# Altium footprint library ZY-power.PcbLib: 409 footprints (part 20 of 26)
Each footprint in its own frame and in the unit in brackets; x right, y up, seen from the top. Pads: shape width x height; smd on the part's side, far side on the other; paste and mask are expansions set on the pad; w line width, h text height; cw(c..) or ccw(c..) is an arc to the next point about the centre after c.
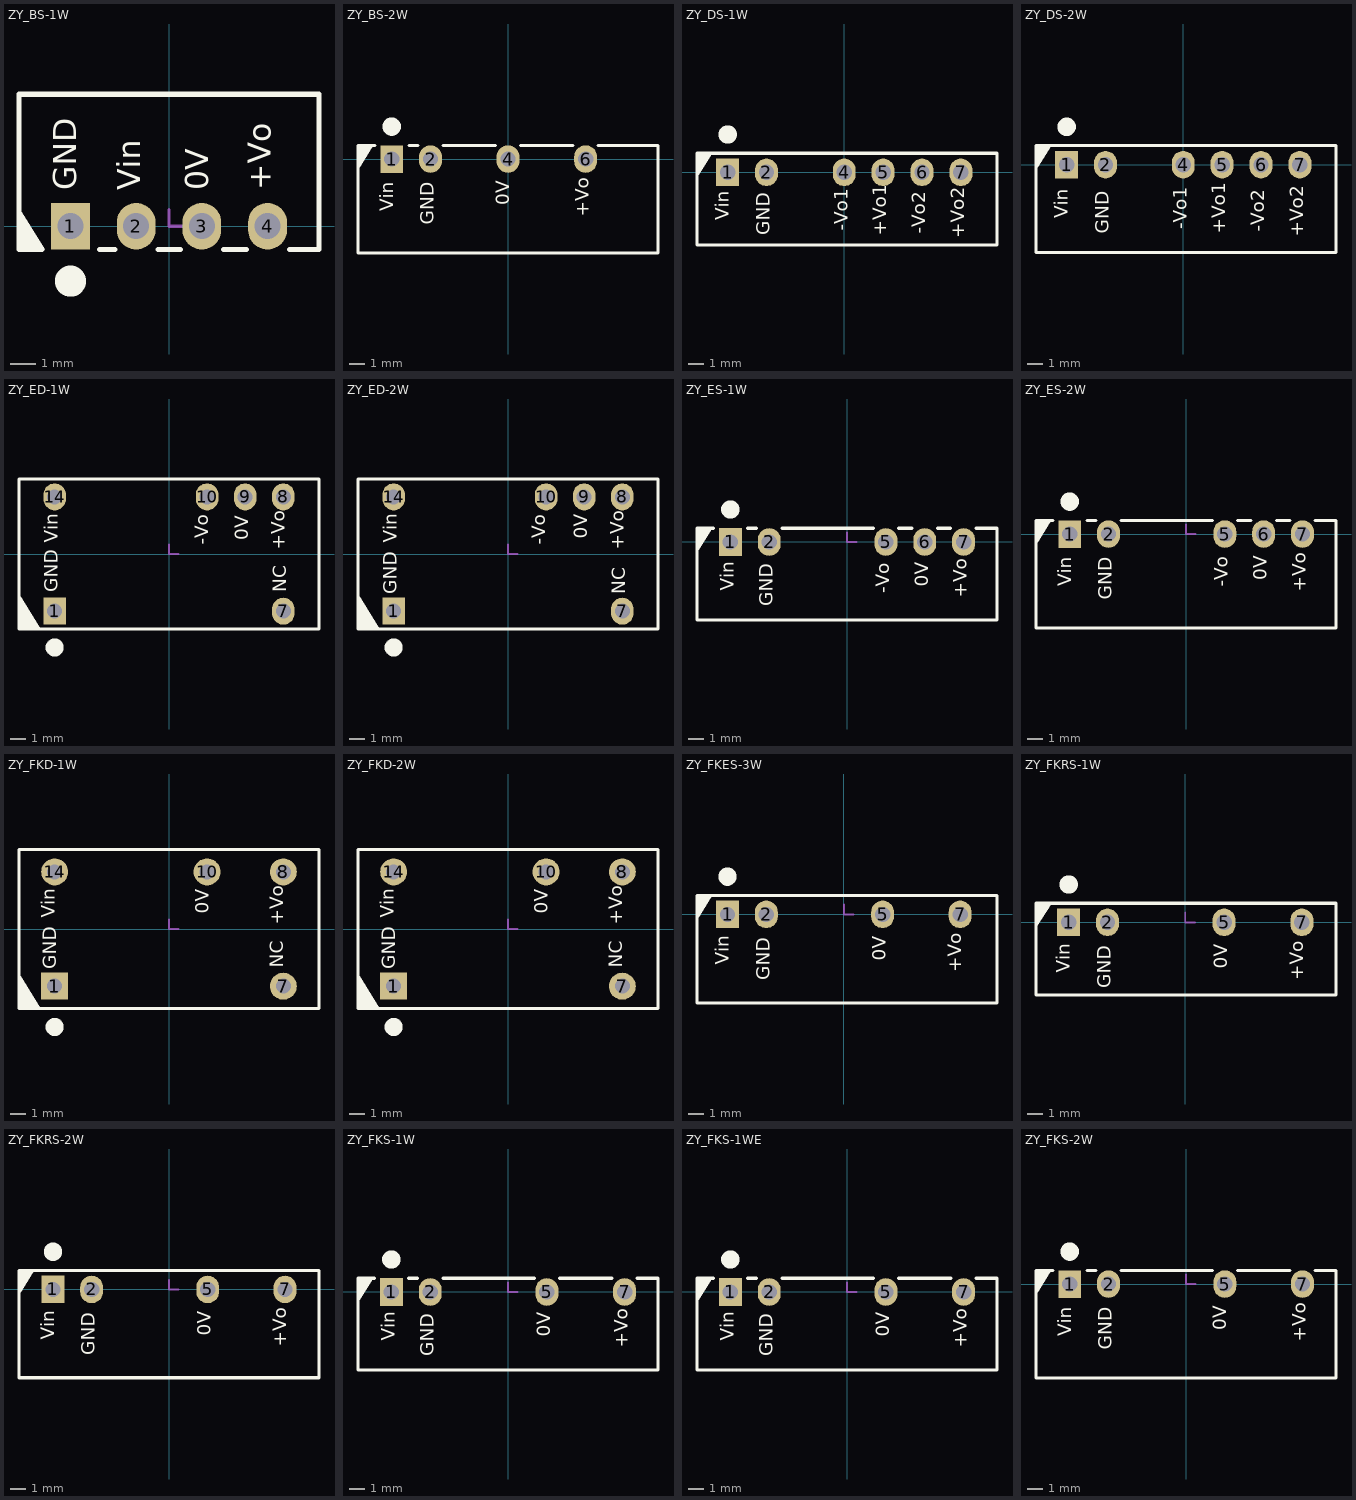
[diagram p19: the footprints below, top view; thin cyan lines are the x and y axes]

## ZY_BS-1W [mm] "定压输入隔离非稳压单输出"
height 10.1
pads (4):
  rect 1.5x1.8 hole 1: 1(-3.81,0)
  oval 1.5x1.8 hole 1: 2(-1.27,0) 3(1.27,0) 4(3.81,0)
Top Overlay:
  circle w1: c-3.81,-2.125 r0.1
  region: -5.8,0.686 -5.8,-0.889 -4.813,-0.889
  lines w0.2: -4.91,-0.9 -5.8,-0.9 -5.8,5.1 5.8,5.1 5.8,-0.9 4.656,-0.9 ; -2.69,-0.9 -2.09,-0.9 ; -0.424,-0.9 0.45,-0.9 ; 2.116,-0.9 2.99,-0.9
  text "GND" at -3.302,1.396 h1.52
  text "Vin" at -0.813,1.397 h1.52
  text "0V" at 1.803,1.396 h1.52
  text "+Vo" at 4.216,1.396 h1.52
Mechanical 15:
  lines w0.127: 0,0.635 0,0 0.635,0
3D body "zhenjao01.stp": height 8.36, standoff -4.08, extent 3.11,-0.12 4.51,1.48
3D body "zhenjao01.stp": height 8.36, standoff -4.08, extent 0.57,-0.12 1.97,1.48
3D body "zhenjao01.stp": height 8.36, standoff -4.08, extent -1.97,-0.12 -0.57,1.48
3D body: height 10.1, standoff 0, extent -5.8,-0.9 5.8,5.1
3D body "zhenjao01.stp": height 8.36, standoff -4.08, extent -4.51,-0.12 -3.11,1.48

## ZY_BS-2W [mm] "定压输入隔离非稳压单输出"
height 10.1
pads (4):
  rect 1.5x1.8 hole 1: 1(-7.62,0)
  oval 1.5x1.8 hole 1: 2(-5.08,0) 4(0,0) 6(5.08,0)
Top Overlay:
  circle w1: c-7.62,2.125 r0.1
  region: -9.83,-0.686 -9.83,0.9 -8.836,0.9
  lines w0.2: -8.72,0.9 -9.83,0.9 -9.83,-6.15 9.82,-6.15 9.82,0.9 5.9,0.9 ; -6.5,0.9 -5.9,0.9 ; -4.26,0.9 -0.82,0.9 ; 0.82,0.9 4.26,0.9
  text "+Vo" at 5.588,-3.776 h1.52
  text "0V" at 0.381,-3.036 h1.52
  text "GND" at -4.572,-4.318 h1.52
  text "Vin" at -7.239,-3.435 h1.52
Mechanical 15:
  lines w0.127: 0,0.635 0,0 0.635,0
3D body: height 10.1, standoff 0, extent -9.83,-6.15 9.77,0.9
3D body "zhenjao01.stp": height 8.36, standoff -4.08, extent 4.38,-1.48 5.78,0.12
3D body "zhenjao01.stp": height 8.36, standoff -4.08, extent -0.7,-1.48 0.7,0.12
3D body "zhenjao01.stp": height 8.36, standoff -4.08, extent -5.78,-1.48 -4.38,0.12
3D body "zhenjao01.stp": height 8.36, standoff -4.08, extent -8.32,-1.48 -6.92,0.12

## ZY_DS-1W [mm]
pads (6):
  rect 1.5x1.8 hole 1: 1(-7.62,0)
  oval 1.5x1.8 hole 1: 2(-5.08,0) 4(0,0) 5(2.54,0) 6(5.08,0) 7(7.62,0)
Top Overlay:
  circle w1: c-7.62,2.475 r0.1
  region: -9.62,-0.336 -9.62,1.25 -8.626,1.25
  lines w0.2: -9.62,-4.75 9.98,-4.75 9.98,1.25 -9.62,1.25 -9.62,-4.75
  text "-Vo1" at 0.508,-3.828 h1.52
  text "Vin" at -7.239,-3.113 h1.52
  text "GND" at -4.572,-4.123 h1.52
  text "+Vo1" at 3.048,-4.14 h1.52
  text "-Vo2" at 5.588,-4.006 h1.52
  text "+Vo2" at 8.128,-4.318 h1.52
Mechanical 15:
  lines w0.127: 0,0.635 0,0 0.635,0

## ZY_DS-2W [mm] "定压输入隔离非稳压双输出"
height 10
pads (6):
  rect 1.5x1.8 hole 1: 1(-7.62,0)
  oval 1.5x1.8 hole 1: 2(-5.08,0) 4(0,0) 5(2.54,0) 6(5.08,0) 7(7.62,0)
Top Overlay:
  circle w1: c-7.62,2.475 r0.1
  region: -9.62,-0.336 -9.62,1.25 -8.626,1.25
  lines w0.2: -9.62,-5.75 -9.62,1.25 9.98,1.25 9.98,-5.75 -9.62,-5.75
  text "+Vo2" at 8.128,-4.699 h1.52
  text "-Vo2" at 5.588,-4.387 h1.52
  text "+Vo1" at 3.048,-4.521 h1.52
  text "GND" at -4.572,-4.504 h1.52
  text "Vin" at -7.239,-3.494 h1.52
  text "-Vo1" at 0.508,-4.209 h1.52
Mechanical 15:
  lines w0.127: 0,0.635 0,0 0.635,0

## ZY_ED-1W [mm] "定压输入隔离非稳压正、负输出"
height 7
pads (6):
  rect 1.5x1.8 hole 1: 1(-7.62,-3.81)
  oval 1.5x1.8 hole 1: 7(7.62,-3.81) 8(7.62,3.81) 9(5.08,3.81) 10(2.54,3.81) 14(-7.62,3.81)
Top Overlay:
  circle w1: c-7.62,-6.225 r0.1
  region: -10,-2.67 -10,-5 -8.54,-5
  lines w0.2: -10,-5 10,-5 10,5 -10,5 -10,-5
  text "+Vo" at 8.001,0.294 h1.52
  text "0V" at 5.588,0.907 h1.52
  text "-Vo" at 2.921,0.606 h1.52
  text "Vin" at -7.112,0.762 h1.52
  text "NC" at 8.128,-2.54 h1.52
  text "GND" at -7.112,-2.54 h1.52
Mechanical 15:
  lines w0.127: 0,0.635 0,0 0.635,0

## ZY_ED-2W [mm]
height 8
pads (6):
  rect 1.5x1.8 hole 1: 1(-7.62,-3.81)
  oval 1.5x1.8 hole 1: 7(7.62,-3.81) 8(7.62,3.81) 9(5.08,3.81) 10(2.54,3.81) 14(-7.62,3.81)
Top Overlay:
  circle w1: c-7.62,-6.225 r0.1
  region: -10,-2.67 -10,-5 -8.54,-5
  lines w0.2: -10,-5 -10,5 10,5 10,-5 -10,-5
  text "GND" at -7.112,-2.667 h1.52
  text "NC" at 8.128,-2.667 h1.52
  text "Vin" at -7.112,0.762 h1.52
  text "-Vo" at 2.794,0.606 h1.52
  text "0V" at 5.588,1.034 h1.52
  text "+Vo" at 8.001,0.294 h1.52
Mechanical 15:
  lines w0.127: 0,0.635 0,0 0.635,0

## ZY_ES-1W [mm] "定压输入隔离非稳压正、负输出"
height 10.1
pads (5):
  rect 1.5x1.8 hole 1: 1(-7.62,0)
  oval 1.5x1.8 hole 1: 2(-5.08,0) 5(2.54,0) 6(5.08,0) 7(7.62,0)
Top Overlay:
  circle w1: c-7.62,2.125 r0.1
  region: -9.8,-0.686 -9.8,0.9 -8.806,0.9
  lines w0.2: -8.72,0.9 -9.8,0.9 -9.8,-5.1 9.8,-5.1 9.8,0.9 8.44,0.9 ; -6.5,0.9 -5.9,0.9 ; -4.26,0.9 1.72,0.9 ; 3.36,0.9 4.234,0.9 ; 5.9,0.9 6.774,0.9
  text "0V" at 5.588,-2.909 h1.52
  text "-Vo" at 3.048,-3.337 h1.52
  text "Vin" at -7.112,-3.181 h1.52
  text "GND" at -4.572,-4.191 h1.52
  text "+Vo" at 8.128,-3.649 h1.52
Mechanical 15:
  lines w0.127: 0,0.635 0,0 0.635,0
3D body "zhenjao01.stp": height 8.36, standoff -4.08, extent 4.38,-1.48 5.78,0.12
3D body "zhenjao01.stp": height 8.36, standoff -4.08, extent -8.32,-1.48 -6.92,0.12
3D body "zhenjao01.stp": height 8.36, standoff -4.08, extent -5.78,-1.48 -4.38,0.12
3D body "zhenjao01.stp": height 8.36, standoff -4.08, extent 1.84,-1.48 3.24,0.12
3D body "zhenjao01.stp": height 8.36, standoff -4.08, extent 6.92,-1.48 8.32,0.12
3D body: height 10.1, standoff 0, extent -9.8,-5.1 9.8,0.9

## ZY_ES-2W [mm] "定压输入隔离非稳压双输出"
height 10.1
pads (5):
  rect 1.5x1.8 hole 1: 1(-7.62,0)
  oval 1.5x1.8 hole 1: 2(-5.08,0) 5(2.54,0) 6(5.08,0) 7(7.62,0)
Top Overlay:
  circle w1: c-7.62,2.125 r0.1
  region: -9.83,-0.686 -9.83,0.9 -8.836,0.9
  lines w0.2: -8.72,0.9 -9.83,0.9 -9.83,-6.15 9.82,-6.15 9.82,0.9 8.44,0.9 ; -6.5,0.9 -5.9,0.9 ; -4.26,0.9 1.72,0.9 ; 3.386,0.9 4.26,0.9 ; 5.926,0.9 6.8,0.9
  text "+Vo" at 8.128,-3.776 h1.52
  text "-Vo" at 3.023,-3.466 h1.52
  text "GND" at -4.572,-4.318 h1.52
  text "Vin" at -7.239,-3.435 h1.52
  text "0V" at 5.563,-3.036 h1.52
Mechanical 15:
  lines w0.127: 0,0.635 0,0 0.635,0
3D body: height 10.1, standoff 0, extent -9.83,-6.15 9.77,0.9
3D body "zhenjao01.stp": height 8.36, standoff -4.08, extent 6.92,-1.48 8.32,0.12
3D body "zhenjao01.stp": height 8.36, standoff -4.08, extent 1.84,-1.48 3.24,0.12
3D body "zhenjao01.stp": height 8.36, standoff -4.08, extent -5.78,-1.48 -4.38,0.12
3D body "zhenjao01.stp": height 8.36, standoff -4.08, extent -8.32,-1.48 -6.92,0.12
3D body "zhenjao01.stp": height 8.36, standoff -4.08, extent 4.38,-1.48 5.78,0.12

## ZY_FKD-1W [mm]
height 8
pads (5):
  rect 1.8x1.8 hole 1: 1(-7.62,-3.81)
  round 1.8 hole 1: 7(7.62,-3.81) 8(7.62,3.81) 10(2.54,3.81) 14(-7.62,3.81)
Top Overlay:
  circle w1: c-7.62,-6.525 r0.1
  region: -10,-2.97 -10,-5.3 -8.54,-5.3
  lines w0.2: -10,-5.3 10,-5.3 10,5.3 -10,5.3 -10,-5.3
  text "GND" at -7.214,-2.692 h1.52
  text "NC" at 7.925,-2.565 h1.52
  text "Vin" at -7.315,0.754 h1.52
  text "0V" at 2.946,1.026 h1.52
  text "+Vo" at 7.925,0.286 h1.52
Mechanical 15:
  lines w0.127: 0,0.635 0,0 0.635,0

## ZY_FKD-2W [mm]
height 8.1
pads (5):
  rect 1.8x1.8 hole 1: 1(-7.62,-3.81)
  round 1.8 hole 1: 7(7.62,-3.81) 8(7.62,3.81) 10(2.54,3.81) 14(-7.62,3.81)
Top Overlay:
  circle w1: c-7.62,-6.525 r0.1
  region: -10,-2.97 -10,-5.3 -8.54,-5.3
  lines w0.2: -10,-5.3 10,-5.3 10,5.3 -10,5.3 -10,-5.3
  text "GND" at -7.214,-2.692 h1.52
  text "NC" at 7.925,-2.565 h1.52
  text "Vin" at -7.315,0.754 h1.52
  text "0V" at 2.946,1.026 h1.52
  text "+Vo" at 7.925,0.286 h1.52
Mechanical 15:
  lines w0.127: 0,0.635 0,0 0.635,0

## ZY_FKES-3W [mm]
pads (4):
  rect 1.5x1.8 hole 1: 1(-7.62,0)
  oval 1.5x1.8 hole 1: 2(-5.08,0) 5(2.54,0) 7(7.62,0)
Top Overlay:
  circle w1: c-7.62,2.475 r0.1
  region: -9.62,-0.336 -9.62,1.25 -8.626,1.25
  lines w0.2: 10.03,-5.797 10.03,1.25 -9.62,1.25 -9.62,-5.8 10.033,-5.8
  text "Vin" at -7.239,-3.308 h1.52
  text "GND" at -4.572,-4.318 h1.52
  text "0V" at 3.048,-3.036 h1.52
  text "+Vo" at 8.001,-3.776 h1.52
Mechanical 15:
  lines w0.127: 0,0.635 0,0 0.635,0

## ZY_FKRS-1W [mm]
height 10
pads (4):
  rect 1.5x1.8 hole 1: 1(-7.62,0)
  oval 1.5x1.8 hole 1: 2(-5.08,0) 5(2.54,0) 7(7.62,0)
Top Overlay:
  circle w1: c-7.62,2.475 r0.1
  region: -9.722,-0.336 -9.722,1.25 -8.728,1.25
  lines w0.2: -9.75,-4.75 9.85,-4.75 9.85,1.25 -9.75,1.25 -9.75,-4.75
  text "+Vo" at 8.001,-3.776 h1.52
  text "0V" at 3.048,-3.036 h1.52
  text "GND" at -4.572,-4.318 h1.52
  text "Vin" at -7.239,-3.308 h1.52
Mechanical 15:
  lines w0.127: 0,0.635 0,0 0.635,0

## ZY_FKRS-2W [mm]
height 10
pads (4):
  rect 1.5x1.8 hole 1: 1(-7.62,0)
  oval 1.5x1.8 hole 1: 2(-5.08,0) 5(2.54,0) 7(7.62,0)
Top Overlay:
  circle w1: c-7.62,2.475 r0.1
  region: -9.85,-0.336 -9.85,1.25 -8.856,1.25
  lines w0.2: -9.85,-5.8 -9.85,1.25 9.85,1.25 9.85,-5.8 -9.85,-5.8
  text "Vin" at -7.239,-3.308 h1.52
  text "GND" at -4.572,-4.318 h1.52
  text "0V" at 3.048,-3.036 h1.52
  text "+Vo" at 8.001,-3.776 h1.52
Mechanical 15:
  lines w0.127: 0,0.635 0,0 0.635,0

## ZY_FKS-1W [mm]
height 10.1
pads (4):
  rect 1.5x1.8 hole 1: 1(-7.62,0)
  oval 1.5x1.8 hole 1: 2(-5.08,0) 5(2.54,0) 7(7.62,0)
Top Overlay:
  circle w1: c-7.62,2.125 r0.1
  region: -9.8,-0.686 -9.8,0.9 -8.806,0.9
  lines w0.2: -8.72,0.9 -9.8,0.9 -9.8,-5.1 9.8,-5.1 9.8,0.9 8.44,0.9 ; -6.5,0.9 -5.9,0.9 ; -4.26,0.9 1.72,0.9 ; 3.36,0.9 6.8,0.9
  text "Vin" at -7.112,-3.181 h1.52
  text "GND" at -4.572,-4.191 h1.52
  text "0V" at 3.048,-2.909 h1.52
  text "+Vo" at 8.128,-3.649 h1.52
Mechanical 15:
  lines w0.127: 0,0.635 0,0 0.635,0
3D body "zhenjao01.stp": height 8.36, standoff -4.08, extent -8.32,-1.48 -6.92,0.12
3D body "zhenjao01.stp": height 8.36, standoff -4.08, extent -5.78,-1.48 -4.38,0.12
3D body "zhenjao01.stp": height 8.36, standoff -4.08, extent 1.84,-1.48 3.24,0.12
3D body "zhenjao01.stp": height 8.36, standoff -4.08, extent 6.92,-1.48 8.32,0.12
3D body: height 10.1, standoff 0, extent -9.8,-5.1 9.8,0.9

## ZY_FKS-1WE [mm]
height 10.1
pads (4):
  rect 1.5x1.8 hole 1: 1(-7.62,0)
  oval 1.5x1.8 hole 1: 2(-5.08,0) 5(2.54,0) 7(7.62,0)
Top Overlay:
  circle w1: c-7.62,2.125 r0.1
  region: -9.8,-0.686 -9.8,0.9 -8.806,0.9
  lines w0.2: -8.72,0.9 -9.8,0.9 -9.8,-5.1 9.8,-5.1 9.8,0.9 8.44,0.9 ; -6.5,0.9 -5.9,0.9 ; -4.26,0.9 1.72,0.9 ; 3.36,0.9 6.8,0.9
  text "+Vo" at 8.128,-3.649 h1.52
  text "0V" at 3.048,-2.909 h1.52
  text "GND" at -4.572,-4.191 h1.52
  text "Vin" at -7.112,-3.181 h1.52
Mechanical 15:
  lines w0.127: 0,0.635 0,0 0.635,0
3D body: height 10.1, standoff 0, extent -9.8,-5.1 9.8,0.9
3D body "zhenjao01.stp": height 8.36, standoff -4.08, extent 6.92,-1.48 8.32,0.12
3D body "zhenjao01.stp": height 8.36, standoff -4.08, extent 1.84,-1.48 3.24,0.12
3D body "zhenjao01.stp": height 8.36, standoff -4.08, extent -5.78,-1.48 -4.38,0.12
3D body "zhenjao01.stp": height 8.36, standoff -4.08, extent -8.32,-1.48 -6.92,0.12

## ZY_FKS-2W [mm] "定压输入隔离非稳压单输出"
height 10.1
pads (4):
  rect 1.5x1.8 hole 1: 1(-7.62,0)
  oval 1.5x1.8 hole 1: 2(-5.08,0) 5(2.54,0) 7(7.62,0)
Top Overlay:
  circle w1: c-7.62,2.125 r0.1
  region: -9.83,-0.686 -9.83,0.9 -8.836,0.9
  lines w0.2: -8.72,0.9 -9.83,0.9 -9.83,-6.15 9.82,-6.15 9.82,0.9 8.44,0.9 ; -6.5,0.9 -5.9,0.9 ; -4.26,0.9 1.72,0.9 ; 3.36,0.9 6.8,0.9
  text "Vin" at -7.239,-3.435 h1.52
  text "GND" at -4.572,-4.318 h1.52
  text "0V" at 2.921,-3.036 h1.52
  text "+Vo" at 8.128,-3.776 h1.52
Mechanical 15:
  lines w0.127: 0,0.635 0,0 0.635,0
3D body "zhenjao01.stp": height 8.36, standoff -4.08, extent -8.32,-1.48 -6.92,0.12
3D body "zhenjao01.stp": height 8.36, standoff -4.08, extent -5.78,-1.48 -4.38,0.12
3D body "zhenjao01.stp": height 8.36, standoff -4.08, extent 1.84,-1.48 3.24,0.12
3D body "zhenjao01.stp": height 8.36, standoff -4.08, extent 6.92,-1.48 8.32,0.12
3D body: height 10.1, standoff 0, extent -9.83,-6.15 9.77,0.9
